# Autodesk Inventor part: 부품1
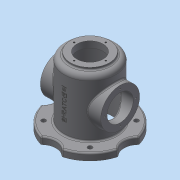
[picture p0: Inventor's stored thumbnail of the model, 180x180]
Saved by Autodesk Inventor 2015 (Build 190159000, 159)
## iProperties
Created: 2022-04
Part Number: 부품1
Material: 일반
Document SubType Name: Modeling
Designer: User
Density: 1 g/cm^3
Appearance: 기본값
Author: User
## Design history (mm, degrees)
sketch "스케치1"
  geometry: C1 r 82 at (0, 0); 1 further point
  constraints: 1 centre point, 1 coincident
  dimensions: "d0" = 164 diameter of C1
extrude "돌출1" new body sketch "스케치1" distance "d1" = 14; taper "d2" = 0 deg
sketch "스케치2"
  geometry: C1 r 30 at (-100, 0); 1 further point
  constraints: 1 centre point, 1 horizontal alignment
  dimensions: "d3" = 60 diameter of C1; "d4" = 100 distance of point (0, 0) C1.centre
extrude "돌출2" cut sketch "스케치2" stored distance "d5" = 14; taper "d6" = 0 deg
sketch "스케치3"
  geometry: L1 (-67.5, 0)-(0, 0); L2 (0, 0)-(-47.73, 47.73); L3 (0, 0)-(0, 67.5); C1 r 4.5 at (-47.73, 47.73); A1 r 67.5 centre (0, 0) between (-67.5, 0) and (-47.73, 47.73); 1 further point
  constraints: 6 end point, 3 point on circle, 2 centre point, 2 coincident, 1 horizontal, 1 perpendicular
  dimensions: "d10" = 135 diameter of A1; "d11" = 45 deg angle of L2 L1; "d12" = 9 diameter of C1
extrude "돌출3" cut sketch "스케치3" stored distance "d13" = 14; taper "d14" = 0 deg
sketch "스케치4"
  geometry: C1 r 53 at (0, 0); 1 further point
  constraints: 1 centre point, 1 coincident
  dimensions: "d18" = 106 diameter of C1
extrude "돌출4" join sketch "스케치4" distance "d19" = 118; taper "d20" = 0 deg
sketch "스케치5"
  geometry: C1 r 40 at (0, 0); 1 further point
  constraints: 1 centre point, 1 coincident
  dimensions: "d21" = 80 diameter of C1
extrude "돌출5" join sketch "스케치5" distance "d22" = 5; taper "d23" = 0 deg
sketch "스케치6"
  geometry: C1 r 27 at (0, 0); 1 further point
  constraints: 1 centre point, 1 coincident
  dimensions: "d24" = 54 diameter of C1
extrude "돌출6" cut sketch "스케치6" stored distance "d25" = 5; taper "d26" = 0 deg
sketch "스케치7"
  geometry: C1 r 45 at (0, 0); 1 further point
  constraints: 1 centre point, 1 coincident
  dimensions: "d27" = 90 diameter of C1
extrude "돌출7" cut sketch "스케치7" distance "d28" = 124; taper "d29" = 0 deg
sketch "스케치8" dims "d30" = 65
  geometry: 3 further points
  constraints: 2 vertical alignment, 1 coincident, 2 other
hole "구멍1" sketch "스케치8" at (0, 32.5) diameter "d31" = 3.242; stored, may be unused: countersink angle "d35" = 90 deg, drill point angle "d37" = 118 deg; dims "d32" = 8, "d33" = 4, "d34" = 2, "d36" = 10
node "작업 평면1"
sketch "스케치9"
  geometry: L1 (21.541, 0)-(-21.541, 0) reference; L2 (21.541, 0)-(79.12, 0) reference; C1 r 40 at (0, 68); 2 further points
  constraints: 1 centre point, 1 midpoint, 1 vertical alignment
  dimensions: "d42" = 80 diameter of C1; "d43" = 68 distance from line of L2 C1.centre
extrude "돌출8" join sketch "스케치9" stored distance "d44" = 124; taper "d45" = 0 deg
sketch "스케치10" dims "d46" = 65
  geometry: 3 further points
  constraints: 2 vertical alignment, 2 other
hole "구멍2" sketch "스케치10" at (0, 32.5) diameter "d47" = 3.242; stored, may be unused: countersink angle "d51" = 90 deg, drill point angle "d53" = 118 deg; dims "d48" = 8, "d49" = 4, "d50" = 2, "d52" = 10
node "작업 평면2"
sketch "스케치11"
  geometry: L1 (-68, -21.541)-(-68, 21.541) reference; C1 r 27 at (0, 0); 2 further points
  constraints: 1 centre point, 1 horizontal alignment, 1 midpoint
  dimensions: "d58" = 54 diameter of C1; "d59" = 68 distance from line of L1 C1.centre
extrude "돌출9" cut sketch "스케치11" stored distance "d60" = 124; taper "d61" = 0 deg
fillet "모깎기1" dims "d62" = 3
fillet "모깎기2" dims "d63" = 3
fillet "모깎기3" dims "d64" = 3
fillet "모깎기4" dims "d65" = 3
fillet "모깎기5" dims "d66" = 10
node "작업 평면3"
node "작업 평면4"
sketch "스케치12"
  geometry: 2 further points
  constraints: 1 vertical alignment, 1 other
  dimensions: "d69" = 70 distance of point (0, 70) point (0, 0)
feature "엠보싱1" sketch "스케치12" dims "d70" = 0.5, "d71" = 0
fillet "모깎기6" dims "d72" = 3
node "솔리드1"
pattern_circular "원형 패턴1" dims angle "d8" = 360 deg
pattern_circular "원형 패턴2" dims angle "d16" = 360 deg
pattern_circular "원형 패턴3" dims angle "d39" = 360 deg
pattern_circular "원형 패턴4" dims angle "d55" = 360 deg
mirror "대칭1"
other parameters: "d41" = 62, "d57" = 0, "d67" = -185, "d68" = 16.75
